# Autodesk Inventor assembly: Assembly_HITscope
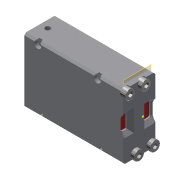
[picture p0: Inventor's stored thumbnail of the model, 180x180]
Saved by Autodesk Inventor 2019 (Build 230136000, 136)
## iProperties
Created: 2021-09
Part Number: Assembly_HITscope
Material: Generisch
Document SubType Name: Assembly
Designer: Muriel
Author: Muriel
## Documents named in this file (4)
- C:\Users\Muriel\Documents\Inventor\HITscope\Assembly_HITscope.iam
- C:\Users\Muriel\Documents\Inventor\HITscope\HITscope_v0.iam
- C:\Users\Muriel\Documents\Inventor\HITscope\02_Camera_Module_Lid_v0.ipt
- C:\Users\Muriel\Documents\Inventor\Content Center Files\R2019\de-DE\DIN 912\DIN 912 - M3 x 0,5 x 8 x 6,75.ipt
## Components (7 placed, 3 different names)
1. 02_Camera_Module_Lid_v0:1 — Einfügen:1, Einfügen:2, Einfügen:3, Einfügen:4
2. HITscope_v0:1 [sub-assembly] — Passend:1, Fluchtend:1, Winkel:1, Fluchtend:2, Fluchtend:3
3. HITscope_v0:3 [sub-assembly] — Passend:1, Fluchtend:1, Winkel:1, Fluchtend:2, Fluchtend:3
4. DIN 912 - ersetzt durch DIN EN ISO 4762 M3 x 8:1 — Einfügen:1
5. DIN 912 - ersetzt durch DIN EN ISO 4762 M3 x 8:2 — Einfügen:2
6. DIN 912 - ersetzt durch DIN EN ISO 4762 M3 x 8:3 — Einfügen:3
7. DIN 912 - ersetzt durch DIN EN ISO 4762 M3 x 8:4 — Einfügen:4
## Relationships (9: Insert 4, Flush 3, Mate 1, Angle 1)
- Passend:1 [Mate]: HITscope_v0:1 ↔ HITscope_v0:3
- Fluchtend:1 [Flush]: HITscope_v0:1 ↔ HITscope_v0:3
- Winkel:1 [Angle]: HITscope_v0:1 ↔ HITscope_v0:3
- Fluchtend:2 [Flush]: HITscope_v0:1 ↔ HITscope_v0:3
- Fluchtend:3 [Flush]: HITscope_v0:1 ↔ HITscope_v0:3
- Einfügen:1 [Insert]: 02_Camera_Module_Lid_v0:1 ↔ DIN 912 - ersetzt durch DIN EN ISO 4762 M3 x 8:1
- Einfügen:2 [Insert]: 02_Camera_Module_Lid_v0:1 ↔ DIN 912 - ersetzt durch DIN EN ISO 4762 M3 x 8:2
- Einfügen:3 [Insert]: 02_Camera_Module_Lid_v0:1 ↔ DIN 912 - ersetzt durch DIN EN ISO 4762 M3 x 8:3
- Einfügen:4 [Insert]: 02_Camera_Module_Lid_v0:1 ↔ DIN 912 - ersetzt durch DIN EN ISO 4762 M3 x 8:4
